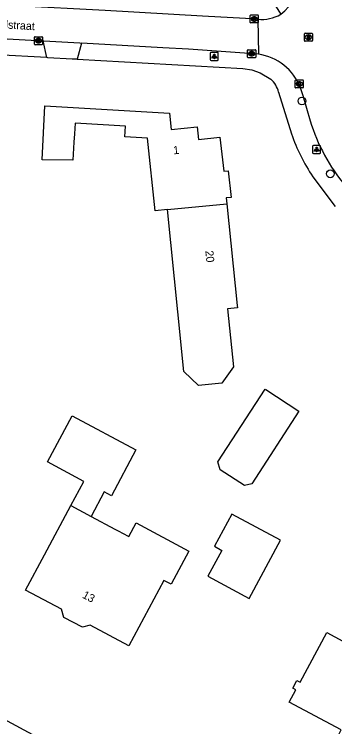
# Model space of a CAD drawing. Extents: x 161258 to 161838, y 380836 to 381727.
# Drawn here: x 161615.9 to 161655.9, y 381097.3 to 381186.3 of the extents above; entities that cross this region are included whole.
import ezdxf

# ---------------------------------------------------------------- set-up
doc = ezdxf.new("R2010")
doc.units = 0
for name, color, linetype in [('IMGEO_Boom', 7, 'Continuous'), ('IMGEO_Kolk', 7, 'Continuous'), ('IMGEO_Lichtpunt', 7, 'Continuous'), ('IMGEO_Openbare_ruimte_label', 7, 'Continuous'), ('IMGEO_Pand', 7, 'Continuous'), ('IMGEO_Pand_nummerreeks', 7, 'Continuous'), ('IMGEO_Rijbaan_lokaal_open', 7, 'Continuous'), ('IMGEO_Rioolput', 7, 'Continuous'), ('IMGEO_Voetpad_open', 7, 'Continuous')]:
    doc.layers.add(name, color=color, linetype=linetype)

msp = doc.modelspace()

# ---------------------------------------------------------------- linework, layer by layer
at = {"layer": 'IMGEO_Boom'}
for centre in [(161651.847, 381175.469), (161655.379, 381166.383)]:
    msp.add_circle(centre, 0.489, dxfattribs=at)
at = {"layer": 'IMGEO_Kolk'}
for p, q in [((161645.466, 381186.206), (161646.318, 381186.206)), ((161645.391, 381185.28), (161645.391, 381186.132)), ((161645.902, 381185.426), (161645.877, 381185.426)), ((161645.879, 381185.986), (161645.904, 381185.986)), ((161646.392, 381186.132), (161646.392, 381185.28)), ((161646.318, 381185.206), (161645.466, 381185.206)), ((161618.531, 381183.499), (161619.383, 381183.499)), ((161618.456, 381182.573), (161618.456, 381183.425)), ((161618.967, 381182.719), (161618.942, 381182.719)), ((161618.944, 381183.279), (161618.969, 381183.279)), ((161619.457, 381183.425), (161619.457, 381182.573)), ((161619.383, 381182.499), (161618.531, 381182.499)), ((161645.064, 381180.948), (161645.064, 381181.8)), ((161645.139, 381181.874), (161645.991, 381181.874)), ((161646.065, 381181.8), (161646.065, 381180.948)), ((161645.991, 381180.874), (161645.139, 381180.874)), ((161645.575, 381181.094), (161645.55, 381181.094)), ((161645.552, 381181.654), (161645.577, 381181.654)), ((161651.012, 381177.168), (161651.012, 381178.02)), ((161651.087, 381178.094), (161651.939, 381178.094)), ((161651.523, 381177.314), (161651.498, 381177.314)), ((161651.5, 381177.874), (161651.525, 381177.874)), ((161652.013, 381178.02), (161652.013, 381177.168)), ((161651.939, 381177.094), (161651.087, 381177.094))]:
    msp.add_line(p, q, dxfattribs=at)
for points in [[(161645.466, 381186.206), (161646.318, 381186.206)], [(161645.391, 381185.28), (161645.391, 381186.132)], [(161645.712, 381185.906), (161645.835, 381185.906), (161645.835, 381185.755), (161645.965, 381185.906), (161646.129, 381185.906), (161645.983, 381185.755), (161646.136, 381185.506), (161645.984, 381185.506), (161645.899, 381185.67), (161645.835, 381185.603), (161645.835, 381185.506), (161645.712, 381185.506), (161645.712, 381185.906)], [(161646.392, 381186.132), (161646.392, 381185.28)], [(161646.318, 381185.206), (161645.466, 381185.206)], [(161618.531, 381183.499), (161619.383, 381183.499)], [(161618.456, 381182.573), (161618.456, 381183.425)], [(161618.777, 381183.199), (161618.9, 381183.199), (161618.9, 381183.048), (161619.03, 381183.199), (161619.194, 381183.199), (161619.048, 381183.048), (161619.201, 381182.799), (161619.049, 381182.799), (161618.964, 381182.963), (161618.9, 381182.896), (161618.9, 381182.799), (161618.777, 381182.799), (161618.777, 381183.199)], [(161619.457, 381183.425), (161619.457, 381182.573)], [(161619.383, 381182.499), (161618.531, 381182.499)], [(161645.064, 381180.948), (161645.064, 381181.8)], [(161645.139, 381181.874), (161645.991, 381181.874)], [(161646.065, 381181.8), (161646.065, 381180.948)], [(161645.991, 381180.874), (161645.139, 381180.874)], [(161645.385, 381181.574), (161645.508, 381181.574), (161645.508, 381181.423), (161645.638, 381181.574), (161645.802, 381181.574), (161645.656, 381181.423), (161645.809, 381181.174), (161645.657, 381181.174), (161645.572, 381181.338), (161645.508, 381181.271), (161645.508, 381181.174), (161645.385, 381181.174), (161645.385, 381181.574)], [(161651.012, 381177.168), (161651.012, 381178.02)], [(161651.087, 381178.094), (161651.939, 381178.094)], [(161651.333, 381177.794), (161651.456, 381177.794), (161651.456, 381177.643), (161651.586, 381177.794), (161651.75, 381177.794), (161651.604, 381177.643), (161651.757, 381177.394), (161651.605, 381177.394), (161651.52, 381177.558), (161651.456, 381177.491), (161651.456, 381177.394), (161651.333, 381177.394), (161651.333, 381177.794)], [(161652.013, 381178.02), (161652.013, 381177.168)], [(161651.939, 381177.094), (161651.087, 381177.094)]]:
    msp.add_lwpolyline(points, dxfattribs=at)
for centre, start, end in [((161645.468, 381186.13), 91.55205, 178.44795), ((161645.468, 381186.13), 91.55205, 178.44795), ((161646.316, 381186.13), 1.55205, 88.44795), ((161646.316, 381186.13), 1.55205, 88.44795), ((161645.468, 381185.282), 181.55205, 268.44795), ((161645.468, 381185.282), 181.55205, 268.44795), ((161646.316, 381185.282), 271.55205, 358.44795), ((161646.316, 381185.282), 271.55205, 358.44795), ((161618.533, 381183.423), 91.55205, 178.44795), ((161618.533, 381183.423), 91.55205, 178.44795), ((161619.381, 381183.423), 1.55205, 88.44795), ((161619.381, 381183.423), 1.55205, 88.44795), ((161618.533, 381182.575), 181.55205, 268.44795), ((161618.533, 381182.575), 181.55205, 268.44795), ((161619.381, 381182.575), 271.55205, 358.44795), ((161619.381, 381182.575), 271.55205, 358.44795), ((161645.141, 381181.798), 91.55205, 178.44795), ((161645.141, 381181.798), 91.55205, 178.44795), ((161645.989, 381181.798), 1.55205, 88.44795), ((161645.989, 381181.798), 1.55205, 88.44795), ((161645.141, 381180.95), 181.55205, 268.44795), ((161645.141, 381180.95), 181.55205, 268.44795), ((161645.989, 381180.95), 271.55205, 358.44795), ((161645.989, 381180.95), 271.55205, 358.44795), ((161651.089, 381178.018), 91.55205, 178.44795), ((161651.089, 381178.018), 91.55205, 178.44795), ((161651.937, 381178.018), 1.55205, 88.44795), ((161651.937, 381178.018), 1.55205, 88.44795), ((161651.089, 381177.17), 181.55205, 268.44795), ((161651.089, 381177.17), 181.55205, 268.44795), ((161651.937, 381177.17), 271.55205, 358.44795), ((161651.937, 381177.17), 271.55205, 358.44795)]:
    msp.add_arc(centre, 0.0765, start, end, dxfattribs=at)
for centre, major_axis, ratio, start_param, end_param in [((161645.878, 381185.706), (-0.387, 0.002), 0.722429, 4.712389, 7.853982), ((161645.903, 381185.706), (-0.39, 0.002), 0.717154, 1.570796, 4.712389), ((161618.943, 381182.999), (-0.387, 0.002), 0.722429, 4.712389, 7.853982), ((161618.968, 381182.999), (-0.39, 0.002), 0.717154, 1.570796, 4.712389), ((161645.551, 381181.374), (-0.387, 0.002), 0.722429, 4.712389, 7.853982), ((161645.576, 381181.374), (-0.39, 0.002), 0.717154, 1.570796, 4.712389), ((161651.499, 381177.594), (-0.387, 0.002), 0.722429, 4.712389, 7.853982), ((161651.524, 381177.594), (-0.39, 0.002), 0.717154, 1.570796, 4.712389)]:
    msp.add_ellipse(centre, major_axis=major_axis, ratio=ratio, start_param=start_param, end_param=end_param, dxfattribs=at)
at = {"layer": 'IMGEO_Lichtpunt'}
for p, q in [((161640.401, 381181.438), (161640.401, 381180.631)), ((161640.401, 381181.438), (161640.401, 381180.631)), ((161641.303, 381181.533), (161640.495, 381181.533)), ((161641.303, 381181.533), (161640.495, 381181.533)), ((161641.397, 381180.631), (161641.397, 381181.438)), ((161641.397, 381180.631), (161641.397, 381181.438)), ((161640.495, 381180.537), (161641.303, 381180.537)), ((161640.495, 381180.537), (161641.303, 381180.537)), ((161653.174, 381169.824), (161653.174, 381169.017)), ((161653.174, 381169.824), (161653.174, 381169.017)), ((161654.076, 381169.919), (161653.268, 381169.919)), ((161654.076, 381169.919), (161653.268, 381169.919)), ((161654.17, 381169.017), (161654.17, 381169.824)), ((161654.17, 381169.017), (161654.17, 381169.824)), ((161653.268, 381168.923), (161654.076, 381168.923)), ((161653.268, 381168.923), (161654.076, 381168.923))]:
    msp.add_line(p, q, dxfattribs=at)
for points in [[(161640.775, 381181.102), (161640.814, 381181.074), (161640.626, 381180.812), (161640.588, 381180.839), (161640.775, 381181.102)], [(161640.877, 381181.054), (161640.924, 381181.054), (161640.924, 381180.732), (161640.877, 381180.732), (161640.877, 381181.054)], [(161640.987, 381181.074), (161641.025, 381181.101), (161641.212, 381180.839), (161641.173, 381180.811), (161640.987, 381181.074)], [(161653.548, 381169.488), (161653.587, 381169.46), (161653.399, 381169.198), (161653.361, 381169.225), (161653.548, 381169.488)], [(161653.65, 381169.44), (161653.697, 381169.44), (161653.697, 381169.118), (161653.65, 381169.118), (161653.65, 381169.44)], [(161653.76, 381169.46), (161653.798, 381169.487), (161653.985, 381169.225), (161653.946, 381169.197), (161653.76, 381169.46)]]:
    msp.add_lwpolyline(points, dxfattribs=at)
for centre in [(161640.9, 381181.236), (161653.673, 381169.622)]:
    msp.add_circle(centre, 0.0994, dxfattribs=at)
for centre, start, end in [((161640.495, 381181.438), 90, 180), ((161640.495, 381181.438), 90, 180), ((161641.303, 381181.438), 0, 90), ((161641.303, 381181.438), 0, 90), ((161640.495, 381180.631), 180, 270), ((161640.495, 381180.631), 180, 270), ((161641.303, 381180.631), 270, 0), ((161641.303, 381180.631), 270, 360), ((161653.268, 381169.824), 90, 180), ((161653.268, 381169.824), 90, 180), ((161654.076, 381169.824), 0, 90), ((161654.076, 381169.824), 0, 90), ((161653.268, 381169.017), 180, 270), ((161653.268, 381169.017), 180, 270), ((161654.076, 381169.017), 270, 0), ((161654.076, 381169.017), 270, 360)]:
    msp.add_arc(centre, 0.0946, start, end, dxfattribs=at)
at = {"layer": 'IMGEO_Pand'}
for points in [[(161635.039, 381161.925), (161633.502, 381161.768), (161632.58, 381170.818), (161629.736, 381170.984), (161629.816, 381172.338), (161623.519, 381172.707), (161623.44, 381171.353), (161623.38, 381170.335), (161623.248, 381168.075), (161619.4, 381168.127), (161619.768, 381174.864), (161635.293, 381173.955), (161635.503, 381171.902), (161638.767, 381172.236), (161638.927, 381170.668), (161641.598, 381170.941), (161642.081, 381166.707), (161642.649, 381166.765), (161642.989, 381163.432), (161642.402, 381163.372), (161642.48, 381162.61)], [(161642.48, 381162.61), (161643.772, 381149.921), (161643.799, 381149.653), (161642.554, 381149.527), (161643.293, 381142.292), (161641.821, 381140.244), (161638.932, 381139.97), (161637.102, 381141.685), (161636.339, 381149.163), (161635.039, 381161.925)], [(161635.039, 381161.925), (161642.48, 381162.61)], [(161645.576, 381127.671), (161644.668, 381127.456), (161641.623, 381129.433), (161641.334, 381130.425), (161647.232, 381139.509), (161647.349, 381139.433), (161651.472, 381136.755), (161645.576, 381127.671)], [(161622.988, 381124.974), (161624.602, 381127.986), (161620.079, 381130.409), (161623.161, 381136.163), (161631.111, 381131.904), (161628.053, 381126.195), (161627.173, 381126.667), (161625.535, 381123.609)], [(161625.535, 381123.609), (161628.478, 381122.033), (161629.005, 381121.75), (161629.456, 381121.509), (161630.232, 381121.093), (161631.15, 381122.808), (161637.721, 381119.288), (161635.505, 381115.148), (161634.613, 381115.626), (161630.241, 381107.461), (161625.408, 381110.049), (161624.458, 381109.762), (161622.137, 381111.004), (161621.833, 381112.011), (161617.336, 381114.419), (161619.696, 381118.827), (161622.988, 381124.974)], [(161622.988, 381124.974), (161625.535, 381123.609)], [(161649.165, 381120.625), (161643.084, 381123.899), (161640.917, 381119.874), (161641.846, 381119.373), (161640.111, 381116.149), (161645.263, 381113.376), (161649.165, 381120.625)], [(161665.322, 381103.509), (161663.01, 381099.191), (161660.649, 381094.783), (161658.583, 381095.89), (161658.309, 381095.378), (161656.425, 381096.386), (161656.736, 381096.967), (161650.259, 381100.435), (161651.075, 381101.959), (161650.701, 381102.159), (161651.21, 381103.11), (161651.598, 381102.902), (161654.932, 381109.096), (161665.322, 381103.509)]]:
    msp.add_lwpolyline(points, dxfattribs=at)
at = {"layer": 'IMGEO_Rijbaan_lokaal_open'}
for points in [[(161646.327, 381185.682), (161639.431, 381186.067), (161627.28, 381186.753), (161616.166, 381187.333), (161601.106, 381188.192), (161599.538, 381188.329), (161594.72, 381188.551), (161578.352, 381189.346)], [(161646.327, 381185.682), (161646.404, 381181.294)], [(161613.779, 381183.287), (161614.308, 381183.254), (161619.552, 381182.967)], [(161619.552, 381182.967), (161619.613, 381182.964), (161624.134, 381182.717), (161624.33, 381182.706)], [(161646.404, 381181.294), (161637.698, 381181.953), (161634.484, 381182.112), (161624.33, 381182.706)], [(161651.629, 381177.144), (161651.959, 381176.147), (161652.868, 381172.999)]]:
    msp.add_lwpolyline(points, dxfattribs=at)
for centre, radius, start, end in [((161645.542, 381191.065), 6, 307.38392, 358.2223), ((161646.849, 381190.2), 4.548, 263.41486, 300.91153), ((161645.562, 381174.87), 6.479, 20.54703, 82.53567), ((161674.848, 381179.665), 22.969, 196.87014, 220.0766)]:
    msp.add_arc(centre, radius, start, end, dxfattribs=at)
at = {"layer": 'IMGEO_Rioolput'}
for p, q in [((161652.149, 381183.006), (161652.149, 381183.858)), ((161652.224, 381183.932), (161653.076, 381183.932)), ((161652.637, 381183.712), (161652.662, 381183.712)), ((161653.15, 381183.858), (161653.15, 381183.006)), ((161653.076, 381182.932), (161652.224, 381182.932)), ((161652.66, 381183.152), (161652.635, 381183.152))]:
    msp.add_line(p, q, dxfattribs=at)
for points in [[(161652.149, 381183.006), (161652.149, 381183.858)], [(161652.224, 381183.932), (161653.076, 381183.932)], [(161652.738, 381183.63), (161652.486, 381183.632), (161652.486, 381183.232)], [(161652.664, 381183.551), (161652.61, 381183.551), (161652.61, 381183.47)], [(161653.15, 381183.858), (161653.15, 381183.006)], [(161653.076, 381182.932), (161652.224, 381182.932)], [(161652.486, 381183.232), (161652.61, 381183.232), (161652.61, 381183.394), (161652.621, 381183.394)], [(161652.61, 381183.47), (161652.662, 381183.47)], [(161652.668, 381183.365), (161652.739, 381183.232), (161652.879, 381183.232), (161652.814, 381183.358)]]:
    msp.add_lwpolyline(points, dxfattribs=at)
for centre, radius, start, end in [((161652.226, 381183.856), 0.0765, 91.55205, 178.44795), ((161652.226, 381183.856), 0.0765, 91.55205, 178.44795), ((161652.646, 381183.659), 0.19, 274.7715, 282.96867), ((161652.67, 381183.455), 0.0964, 77.00612, 93.18647), ((161652.684, 381183.512), 0.0378, 276.66336, 79.67722), ((161652.737, 381183.52), 0.109, 350.36119, 89.41601), ((161652.735, 381183.52), 0.112, 277.58423, 350.98172), ((161653.074, 381183.856), 0.0765, 1.55205, 88.44795), ((161653.074, 381183.856), 0.0765, 1.55205, 88.44795), ((161652.226, 381183.008), 0.0765, 181.55205, 268.44795), ((161652.226, 381183.008), 0.0765, 181.55205, 268.44795), ((161652.62, 381183.341), 0.0533, 26.02933, 88.69889), ((161652.719, 381183.305), 0.108, 29.51342, 73.79051), ((161653.074, 381183.008), 0.0765, 271.55205, 358.44795), ((161653.074, 381183.008), 0.0765, 271.55205, 358.44795)]:
    msp.add_arc(centre, radius, start, end, dxfattribs=at)
for centre, major_axis, ratio, start_param, end_param in [((161652.636, 381183.432), (-0.387, 0.002), 0.722429, 4.712389, 7.853982), ((161652.661, 381183.432), (-0.39, 0.002), 0.717154, 1.570796, 4.712389)]:
    msp.add_ellipse(centre, major_axis=major_axis, ratio=ratio, start_param=start_param, end_param=end_param, dxfattribs=at)
at = {"layer": 'IMGEO_Voetpad_open'}
for points in [[(161647.155, 381189.49), (161649.185, 381186.298)], [(161619.983, 381180.882), (161619.552, 381182.967)], [(161624.33, 381182.706), (161623.777, 381180.672)], [(161619.983, 381180.882), (161613.67, 381181.233)], [(161623.777, 381180.672), (161623.141, 381180.707), (161620.13, 381180.874), (161619.983, 381180.882)], [(161623.777, 381180.672), (161644.471, 381179.523), (161645.578, 381179.365), (161646.63, 381178.987), (161647.96, 381178.184)], [(161648.912, 381176.58), (161650.537, 381171.376)], [(161653.21, 381166.017), (161656.002, 381162.313)], [(161686.794, 381059.495), (161683.729, 381060.833), (161676.825, 381064.703), (161608.252, 381101.703), (161603.367, 381104.463), (161599.292, 381107.15)]]:
    msp.add_lwpolyline(points, dxfattribs=at)
for centre, radius, start, end in [((161646.175, 381176.04), 2.789, 11.15751, 50.22212), ((161671.874, 381178.673), 22.551, 198.87902, 214.13983)]:
    msp.add_arc(centre, radius, start, end, dxfattribs=at)

# ---------------------------------------------------------------- texts
at = {"layer": 'IMGEO_Openbare_ruimte_label'}
msp.add_text('Spieghelstraat', height=1, rotation=356.73115, dxfattribs=at).set_placement((161609.932, 381184.797))
at = {"layer": 'IMGEO_Pand_nummerreeks'}
for s, rotation, p in [('1', 5.84417, (161635.816, 381168.802)), ('20', 275.81558, (161639.779, 381156.753)), ('13', 331.66724, (161624.337, 381113.507))]:
    msp.add_text(s, height=1, rotation=rotation, dxfattribs=at).set_placement(p)

doc.saveas('drawing.dxf')
